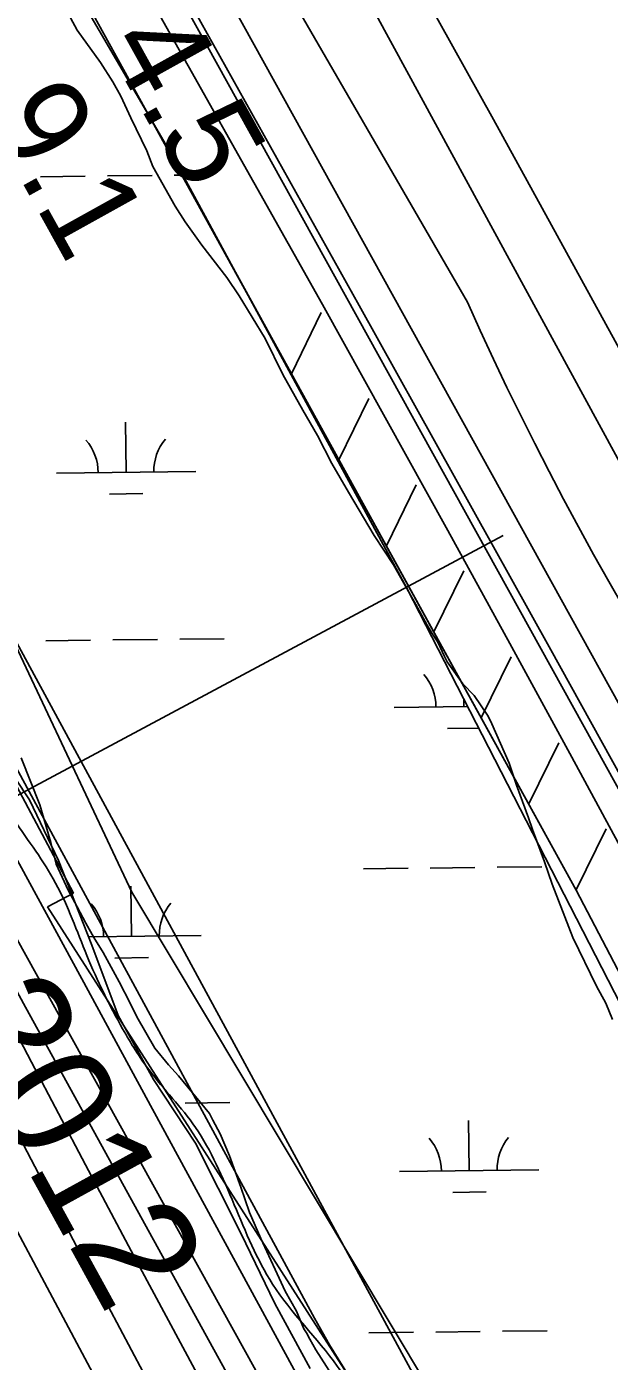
# Model space of a CAD drawing. Extents: x 3684037 to 3722149, y 433263 to 459021.
# Drawn here: x 3712383 to 3712801, y 439267 to 440224 of the extents above; entities that cross this region are included whole.
import ezdxf

# ---------------------------------------------------------------- set-up
doc = ezdxf.new("R2010")
doc.units = 0
for name, color, linetype in [('V-FLOD-BASE', 7, 'Continuous'), ('V-LEVE-TOET', 7, 'Continuous'), ('V-RIVR-EDGE', 7, 'Continuous'), ('V-RIVR-IDEN', 7, 'Continuous'), ('V-RIVR-RANG', 7, 'Continuous'), ('V-ROAD-CNTR', 7, 'Continuous'), ('V-RRAP-FSHR', 7, 'Continuous'), ('V-RRAP-RVMT', 7, 'Continuous'), ('V-SITE-VEGE', 7, 'Continuous'), ('V-SURV-LINE', 7, 'Continuous'), ('V-TOPO-DPTH', 7, 'Continuous'), ('V-TOPO-MINR', 7, 'Continuous'), ('V-TOPO-WATR', 7, 'Continuous'), ('V-UTIL-IDEN', 7, 'Continuous'), ('V-WETL-SWMP', 7, 'Continuous')]:
    doc.layers.add(name, color=color, linetype=linetype)

msp = doc.modelspace()

# ---------------------------------------------------------------- linework, layer by layer
at = {"layer": 'V-FLOD-BASE'}
for points in [[(3712621.19, 440024.51), (3712489.35, 440260.24), (3712460.31, 440309.47)], [(3713166.87, 438967.27), (3713140.61, 439026), (3713120.53, 439071.3), (3713100.22, 439116.51), (3713079.69, 439161.61), (3713058.93, 439206.61), (3713037.95, 439251.51), (3713016.74, 439296.3), (3712995.31, 439340.99), (3712973.66, 439385.56), (3712923.99, 439475.9), (3712874.6, 439566.38), (3712825.48, 439657.01), (3712757.58, 439779.62), (3712689.48, 439902.12), (3712621.19, 440024.51)]]:
    msp.add_lwpolyline(points, dxfattribs=at)
at = {"layer": 'V-LEVE-TOET'}
for points in [[(3711516.68, 442246.95), (3711627.09, 442006.55), (3711773.51, 441696.66), (3711965.19, 441335.23), (3712141.19, 441012.62), (3712263.15, 440800.06), (3712414.75, 440519.15), (3712489.08, 440395.79), (3712504.77, 440365.67), (3712551.23, 440281.69), (3712698.85, 440026.88)], [(3712594.9, 440025.08), (3712449.12, 440283.98), (3712438.67, 440303.09), (3712428.22, 440316.99), (3712416.03, 440329.72), (3712408.48, 440342.46), (3712402.09, 440356.95), (3712396.85, 440373.75), (3712391.04, 440388.23), (3712382.9, 440407.34), (3712366.65, 440432.25), (3712222.6, 440696.36), (3712039.64, 441028.82), (3711814.87, 441429.61), (3711723.69, 441588.89), (3711716.72, 441602.79), (3711694.64, 441649.13), (3711565.06, 441926.01), (3711441.87, 442202.32)], [(3712594.9, 440025.08), (3712639.93, 439944.15), (3712684.75, 439863.11), (3712729.36, 439781.95), (3712773.76, 439700.68), (3712817.94, 439619.29), (3712860.09, 439541.58), (3712902.44, 439463.98), (3712945.01, 439386.5), (3712956.33, 439363.85), (3712967.47, 439341.09), (3712978.41, 439318.25), (3712989.17, 439295.32), (3712999.74, 439272.29), (3713010.11, 439249.19), (3713020.3, 439225.99), (3713030.29, 439202.71), (3713040.09, 439179.35), (3713064.86, 439124.73), (3713089.81, 439070.2), (3713114.95, 439015.75), (3713137.67, 438966.93)], [(3712811.69, 439806.93), (3712800.46, 439826.41), (3712789.42, 439845.99), (3712778.57, 439865.69), (3712767.92, 439885.49), (3712757.46, 439905.4), (3712747.2, 439925.4), (3712737.13, 439945.51), (3712727.26, 439965.71), (3712717.59, 439986.01), (3712708.12, 440006.4), (3712698.85, 440026.88)]]:
    msp.add_lwpolyline(points, dxfattribs=at)
at = {"layer": 'V-RIVR-EDGE'}
msp.add_spline([(3710881.85, 442907.17), (3710900.3, 442872.76), (3710912.89, 442844.25), (3710926.84, 442815.27), (3710939.89, 442789.92), (3710950.22, 442762.31), (3710961.88, 442723.85), (3710972.69, 442706.64), (3710987.55, 442681.29), (3711004.19, 442645.52), (3711013.15, 442612.95), (3711017.62, 442590.33), (3711028.39, 442559.55), (3711043.23, 442525.61), (3711061.24, 442493.46), (3711083.32, 442464.01), (3711101.79, 442435.48), (3711123.37, 442385.69), (3711146.29, 442329.57), (3711160.2, 442285.22), (3711177.71, 442238.15), (3711205.6, 442178.4), (3711227.63, 442127.25), (3711258.71, 442079.24), (3711273.08, 442038.51), (3711277.08, 442009.57), (3711279.27, 441982.43), (3711285.11, 441965.69), (3711299.53, 441946.66), (3711314.4, 441925.82), (3711322.93, 441901.39), (3711344.09, 441864.26), (3711361.61, 441818.09), (3711381.38, 441766.05), (3711387.6, 441724.88), (3711408.3, 441685.04), (3711430.33, 441634.35), (3711446.97, 441597.23), (3711483.42, 441524.79), (3711505.9, 441474.1), (3711521.64, 441439.69), (3711545.49, 441393.97), (3711577.41, 441319.28), (3711605.29, 441255.01), (3711666.49, 441137.74), (3711693.94, 441084.32), (3711722.25, 441011.45), (3711736.18, 440977.51), (3711773.54, 440908.24), (3711800.07, 440850.29), (3711813.99, 440812.28), (3711827.94, 440785.11), (3711836.49, 440767.46), (3711872.07, 440711.3), (3711903.57, 440647.92), (3711936.4, 440576.4), (3711963.82, 440513.48), (3711991.74, 440467.29), (3712009.3, 440437.41), (3712020.05, 440394.43), (3712026.76, 440365.47), (3712043.42, 440336.04), (3712066.37, 440292.58), (3712088.89, 440257.25), (3712109.18, 440235.05), (3712138.9, 440183.88), (3712150.57, 440149.03), (3712155.9, 440111.04), (3712162.18, 440090.68), (3712177.89, 440044.52), (3712191.39, 440016), (3712212.53, 439972.54), (3712246.76, 439918.65), (3712265.21, 439881.98), (3712282.72, 439834), (3712320.51, 439756.14), (3712342.1, 439710.42), (3712373.62, 439655.63), (3712403.35, 439610.34), (3712425.83, 439558.28), (3712451.47, 439505.77), (3712470.39, 439476.33), (3712503.75, 439435.1), (3712518.6, 439408.84), (3712544.23, 439350.45), (3712559.09, 439322.83), (3712605.51, 439263.94), (3712623.98, 439233.6), (3712641.51, 439193.31), (3712662.18, 439142.17), (3712689.17, 439086.03), (3712722.5, 439033.5), (3712753.58, 438981.88), (3712765.15, 438962.6)], degree=3, dxfattribs=at)
at = {"layer": 'V-RIVR-RANG'}
msp.add_line((3712724.5, 439859.46), (3711895.41, 439416.5), dxfattribs=at)
at = {"layer": 'V-ROAD-CNTR'}
msp.add_lwpolyline([(3710393.02, 444727.69), (3710641.61, 444250), (3710817.86, 443893.88), (3711037.73, 443419.98), (3711197.76, 443070.03), (3711490.99, 442422.97), (3711750.12, 441857.32), (3711840.88, 441668.92), (3712186.17, 441036.48), (3712590.75, 440311.07), (3712879.98, 439780.16), (3713036.49, 439491.2), (3713175.22, 439193.41), (3713278.17, 438972.16)], dxfattribs=at)
at = {"layer": 'V-RRAP-FSHR'}
for p, q in [((3712572.55, 439975.43), (3712594.02, 440019.29)), ((3712572.55, 439975.43), (3712594.02, 440019.29)), ((3712606.63, 439913.76), (3712628.1, 439957.61)), ((3712606.63, 439913.76), (3712628.1, 439957.61)), ((3712640.7, 439852.08), (3712662.17, 439895.94)), ((3712640.7, 439852.08), (3712662.17, 439895.94)), ((3712674.78, 439790.41), (3712696.24, 439834.27)), ((3712674.78, 439790.41), (3712696.24, 439834.27)), ((3712708.85, 439728.74), (3712730.32, 439772.6)), ((3712708.85, 439728.74), (3712730.32, 439772.6)), ((3712742.92, 439667.06), (3712764.39, 439710.92)), ((3712742.92, 439667.06), (3712764.39, 439710.92)), ((3712777, 439605.39), (3712798.46, 439649.25)), ((3712777, 439605.39), (3712798.46, 439649.25))]:
    msp.add_line(p, q, dxfattribs=at)
for points in [[(3710219.36, 444700.16), (3710405.05, 444328.82), (3710632.08, 443905.61), (3710829.82, 443472.46), (3710874.19, 443372.05), (3710940.18, 443211.19), (3711150.7, 442775.78), (3711369.41, 442270.41), (3711583.94, 441827.2), (3711640.29, 441693.5), (3711911.6, 441196.46), (3712334.08, 440407.06), (3712777.04, 439605.31), (3712909.03, 439353.17), (3713100.31, 438966.64)], [(3710449.88, 443948.54), (3711032.4, 442732.84), (3711461.51, 441700.35), (3711800.31, 440955.81), (3712037.99, 440494.59), (3712458, 439603.75), (3712696.92, 439205.07), (3712836.7, 438963.43)], [(3712532.33, 440048.23), (3712777.04, 439605.31), (3712909.03, 439353.17), (3713100.31, 438966.64)]]:
    msp.add_lwpolyline(points, dxfattribs=at)
at = {"layer": 'V-RRAP-RVMT'}
for p, q in [((3712349.23, 439728.84), (3712416.17, 439603.02)), ((3712416.17, 439603.02), (3712397.44, 439593.28)), ((3712397.44, 439593.28), (3712704.29, 439115.64))]:
    msp.add_line(p, q, dxfattribs=at)
at = {"layer": 'V-SITE-VEGE'}
for p, q in [((3712414.12, 440230.75), (3712418.88, 440221.89)), ((3712418.88, 440221.89), (3712435.46, 440198.62)), ((3712435.46, 440198.62), (3712444.47, 440184.65)), ((3712444.47, 440184.65), (3712450.17, 440174.4)), ((3712450.17, 440174.4), (3712457.32, 440159.01)), ((3712457.32, 440159.01), (3712468.75, 440135.23)), ((3712468.75, 440135.23), (3712473.06, 440124.03)), ((3712473.06, 440124.03), (3712489.21, 440095.6)), ((3712489.21, 440095.6), (3712496.32, 440084.43)), ((3712496.32, 440084.43), (3712508.17, 440067.67)), ((3712508.17, 440067.67), (3712526.15, 440044.41)), ((3712526.15, 440044.41), (3712535.15, 440031.38)), ((3712535.15, 440031.38), (3712553.66, 440000.63)), ((3712553.66, 440000.63), (3712566.52, 439974.99)), ((3712566.52, 439974.99), (3712580.77, 439949.36)), ((3712580.77, 439949.36), (3712591.22, 439931.18)), ((3712591.22, 439931.18), (3712601.68, 439911.14)), ((3712601.68, 439911.14), (3712613.56, 439890.64)), ((3712613.56, 439890.64), (3712632.07, 439859.42)), ((3712632.07, 439859.42), (3712645.82, 439838.47)), ((3712645.82, 439838.47), (3712661.97, 439810.05)), ((3712661.97, 439810.05), (3712670.06, 439795.13)), ((3712670.06, 439795.13), (3712674.33, 439788.15)), ((3712674.33, 439788.15), (3712677.65, 439783.02)), ((3712677.65, 439783.02), (3712682.41, 439772.76)), ((3712682.41, 439772.76), (3712684.32, 439769.03)), ((3712684.32, 439769.03), (3712695.68, 439753.21)), ((3712695.68, 439753.21), (3712703.71, 439744.85)), ((3712703.71, 439744.85), (3712713.67, 439729.95)), ((3712713.67, 439729.95), (3712716.52, 439724.36)), ((3712716.52, 439724.36), (3712728.92, 439696.37)), ((3712392.1, 439666.44), (3712378.71, 439700.03)), ((3712728.92, 439696.37), (3712734.2, 439680.49)), ((3712734.2, 439680.49), (3712742.82, 439657.16)), ((3712394.99, 439656.63), (3712392.1, 439666.44)), ((3712399.81, 439639.35), (3712394.99, 439656.63)), ((3712742.82, 439657.16), (3712745.7, 439648.75)), ((3712745.7, 439648.75), (3712754.32, 439625.42)), ((3712403.68, 439623.93), (3712399.81, 439639.35)), ((3712412.27, 439605.27), (3712403.68, 439623.93)), ((3712754.32, 439625.42), (3712759.6, 439609.54)), ((3712418.92, 439593.16), (3712412.27, 439605.27)), ((3712759.6, 439609.54), (3712768.69, 439586.21)), ((3712425.1, 439581.5), (3712418.92, 439593.16)), ((3712768.69, 439586.21), (3712774.43, 439571.28)), ((3712430.8, 439571.25), (3712425.1, 439581.5)), ((3712437.44, 439560.54), (3712430.8, 439571.25)), ((3712774.43, 439571.28), (3712791.57, 439536.31)), ((3712448.85, 439539.57), (3712437.44, 439560.54)), ((3712456.94, 439524.18), (3712448.85, 439539.57)), ((3712791.57, 439536.31), (3712798.23, 439524.19)), ((3712461.7, 439514.39), (3712456.94, 439524.18)), ((3712798.23, 439524.19), (3712803.01, 439512.53)), ((3712474.52, 439492.03), (3712461.7, 439514.39)), ((3712484.46, 439479.94), (3712474.52, 439492.03)), ((3712491.54, 439472.04), (3712484.46, 439479.94)), ((3712513.77, 439445.07), (3712491.54, 439472.04)), ((3712516.15, 439440.4), (3712513.77, 439445.07)), ((3712521.38, 439430.62), (3712516.15, 439440.4)), ((3712528.07, 439414.75), (3712521.38, 439430.62)), ((3712536.21, 439392.35), (3712528.07, 439414.75)), ((3712542.45, 439374.14), (3712536.21, 439392.35)), ((3712550.56, 439355.48), (3712542.45, 439374.14)), ((3712568.19, 439317.71), (3712550.56, 439355.48)), ((3712576.27, 439303.26), (3712568.19, 439317.71)), ((3712581.52, 439290.66), (3712576.27, 439303.26)), ((3712583.42, 439287.87), (3712581.52, 439290.66)), ((3712585.8, 439283.21), (3712583.42, 439287.87)), ((3712590.07, 439275.75), (3712585.8, 439283.21)), ((3712610.94, 439243.15), (3712590.07, 439275.75))]:
    msp.add_line(p, q, dxfattribs=at)
at = {"layer": 'V-SURV-LINE'}
for points in [[(3711755.82, 441636.9), (3712986.54, 439416.05)], [(3712960.3, 439401.52), (3711729.57, 441622.37)]]:
    msp.add_lwpolyline(points, dxfattribs=at)
at = {"layer": 'V-TOPO-DPTH'}
for points in [[(3712711.91, 438961.98), (3712683.26, 439014.44), (3712669.9, 439038.84), (3712656.51, 439063.23), (3712643.07, 439087.58), (3712629.6, 439111.92), (3712159.9, 439958.74), (3711790.59, 440757.32)], [(3711790.59, 440757.32), (3712159.9, 439958.74), (3712629.6, 439111.92), (3712643.07, 439087.58), (3712656.51, 439063.23), (3712669.9, 439038.84), (3712683.26, 439014.44), (3712711.91, 438961.98)], [(3712775.94, 438962.72), (3712772.45, 438970), (3712768.37, 438979.09), (3712764.64, 438988.33), (3712761.15, 438997.67), (3712756.93, 439009.65), (3712755.87, 439013.11), (3712755, 439016.6), (3712754.42, 439020.15), (3712754.04, 439023.75), (3712753.61, 439027.32), (3712752.94, 439030.84), (3712751.9, 439034.26), (3712599.91, 439279.32), (3712589.26, 439298.44), (3712232.32, 439956.11), (3712223.41, 439972.67), (3712214.6, 439989.28), (3712205.92, 440005.96), (3712197.32, 440022.68), (3711902.32, 440602.62)], [(3712630.61, 438961.03), (3712603, 439008.9), (3712598.54, 439016.71), (3712594.12, 439024.53), (3712589.75, 439032.38), (3712585.42, 439040.26), (3712508.55, 439181.19), (3712466.17, 439259.74), (3712424.26, 439338.53), (3712383.05, 439417.7), (3712342.32, 439497.11), (3712140.47, 439895.05), (3712130.14, 439915.69), (3712119.96, 439936.41), (3712109.99, 439957.23), (3712100.18, 439978.12), (3711852.57, 440512.66)], [(3711852.57, 440512.66), (3712100.18, 439978.12), (3712109.99, 439957.23), (3712119.96, 439936.41), (3712130.14, 439915.69), (3712140.47, 439895.05), (3712342.32, 439497.11), (3712383.05, 439417.7), (3712424.26, 439338.53), (3712466.17, 439259.74), (3712508.55, 439181.19), (3712585.42, 439040.26), (3712589.75, 439032.38), (3712594.12, 439024.53), (3712598.54, 439016.71), (3712603, 439008.9), (3712630.61, 438961.03)], [(3711979.56, 440292.74), (3712019.96, 440206.64), (3712060.55, 440120.63), (3712133.23, 439967.27), (3712137.67, 439958.03), (3712142.19, 439948.84), (3712146.81, 439939.69), (3712151.5, 439930.58), (3712386.11, 439482), (3712424.88, 439408.36), (3712463.91, 439334.85), (3712503.34, 439261.56), (3712543.03, 439188.41), (3712582.5, 439116.14), (3712602.71, 439079.27), (3712623, 439042.43), (3712643.4, 439005.66), (3712663.88, 438968.93), (3712666.87, 438963.6), (3712668.06, 438961.47)], [(3711979.56, 440292.74), (3712019.96, 440206.64), (3712060.55, 440120.63), (3712133.23, 439967.27), (3712137.67, 439958.03), (3712142.19, 439948.84), (3712146.81, 439939.69), (3712151.5, 439930.58), (3712386.11, 439482), (3712424.88, 439408.36), (3712463.91, 439334.85), (3712503.34, 439261.56), (3712543.03, 439188.41), (3712582.5, 439116.14), (3712602.71, 439079.27), (3712623, 439042.43), (3712643.4, 439005.66), (3712663.88, 438968.93), (3712666.87, 438963.6), (3712668.06, 438961.47)], [(3712590.85, 438960.57), (3712590.74, 438960.77), (3712577.83, 438983.59), (3712565.06, 439006.49), (3712552.48, 439029.5), (3712540.03, 439052.58), (3712182.61, 439722.15), (3712165.69, 439754.27), (3712148.99, 439786.51), (3712132.64, 439818.92), (3712116.52, 439851.46), (3712100.72, 439884.15), (3712085.12, 439916.94), (3712069.84, 439949.87), (3712054.75, 439982.89), (3712000.27, 440103.65), (3711958.26, 440197.2), (3711916.46, 440290.85)], [(3712590.85, 438960.57), (3712590.74, 438960.77), (3712577.83, 438983.59), (3712565.06, 439006.49), (3712552.48, 439029.5), (3712540.03, 439052.58), (3712182.61, 439722.15), (3712165.69, 439754.27), (3712148.99, 439786.51), (3712132.64, 439818.92), (3712116.52, 439851.46), (3712100.72, 439884.15), (3712085.12, 439916.94), (3712069.84, 439949.87), (3712054.75, 439982.89), (3712000.27, 440103.65), (3711958.26, 440197.2), (3711916.46, 440290.85)]]:
    msp.add_lwpolyline(points, dxfattribs=at)
at = {"layer": 'V-TOPO-MINR'}
for points in [[(3712690.03, 438961.73), (3712670.77, 438996.58), (3712655.24, 439024.69), (3712639.72, 439052.81), (3712624.21, 439080.94), (3712608.71, 439109.07), (3712381.75, 439521.26), (3712342.55, 439592.95), (3712303.64, 439664.79), (3712265.15, 439736.86), (3712226.94, 439809.08), (3712155.72, 439944.67), (3712153.36, 439949.22), (3712151.04, 439953.79), (3712148.78, 439958.39), (3712146.55, 439963), (3712109.43, 440041.15), (3712088.74, 440084.88), (3712068.15, 440128.66), (3712047.7, 440172.51), (3712027.35, 440216.4), (3711775.13, 440762.6)], [(3712711.91, 438961.98), (3712683.26, 439014.44), (3712669.9, 439038.84), (3712656.51, 439063.23), (3712643.07, 439087.58), (3712629.6, 439111.92), (3712159.9, 439958.74), (3711790.59, 440757.32)], [(3712630.61, 438961.03), (3712603, 439008.9), (3712598.54, 439016.71), (3712594.12, 439024.53), (3712589.75, 439032.38), (3712585.42, 439040.26), (3712508.55, 439181.19), (3712466.17, 439259.74), (3712424.26, 439338.53), (3712383.05, 439417.7), (3712342.32, 439497.11), (3712140.47, 439895.05), (3712130.14, 439915.69), (3712119.96, 439936.41), (3712109.99, 439957.23), (3712100.18, 439978.12), (3711852.57, 440512.66)], [(3712668.06, 438961.47), (3712666.87, 438963.6), (3712663.88, 438968.93), (3712643.4, 439005.66), (3712623, 439042.43), (3712602.71, 439079.27), (3712582.5, 439116.14), (3712543.03, 439188.41), (3712503.34, 439261.56), (3712463.91, 439334.85), (3712424.88, 439408.36), (3712386.11, 439482), (3712151.5, 439930.58), (3712146.81, 439939.69), (3712142.19, 439948.84), (3712137.67, 439958.03), (3712133.23, 439967.27), (3712060.55, 440120.63), (3712019.96, 440206.64), (3711979.56, 440292.74)], [(3712590.85, 438960.57), (3712590.74, 438960.77), (3712577.83, 438983.59), (3712565.06, 439006.49), (3712552.48, 439029.5), (3712540.03, 439052.58), (3712182.61, 439722.15), (3712165.69, 439754.27), (3712148.99, 439786.51), (3712132.64, 439818.92), (3712116.52, 439851.46), (3712100.72, 439884.15), (3712085.12, 439916.94), (3712069.84, 439949.87), (3712054.75, 439982.89), (3712000.27, 440103.65), (3711958.26, 440197.2), (3711916.46, 440290.85)], [(3712736.43, 438962.27), (3712712.94, 439006.14), (3712694.4, 439040.69), (3712675.81, 439075.2), (3712657.14, 439109.68), (3712638.42, 439144.12), (3712574.33, 439261.75), (3712523.55, 439355.01), (3712472.81, 439448.28), (3712422.11, 439541.59), (3712371.45, 439634.91), (3712220.08, 439913.93), (3712203.92, 439944.11), (3712187.99, 439974.41), (3712172.4, 440004.88), (3712157.04, 440035.47), (3712087.75, 440175.37), (3712038.19, 440276.14)], [(3712819.96, 438963.24), (3712375.6, 439782.6), (3712346.28, 439817.89), (3712320, 439855.5), (3712295.75, 439894.66), (3712242.22, 439989.76), (3712239.06, 439995.47), (3712235.95, 440001.21), (3712232.94, 440007), (3712229.97, 440012.81), (3712146.88, 440178.99), (3712102.85, 440268.13)]]:
    msp.add_lwpolyline(points, dxfattribs=at)
at = {"layer": 'V-TOPO-WATR'}
msp.add_lwpolyline([(3712775.94, 438962.72), (3712772.45, 438970), (3712768.37, 438979.09), (3712764.64, 438988.33), (3712761.15, 438997.67), (3712756.93, 439009.65), (3712755.87, 439013.11), (3712755, 439016.6), (3712754.42, 439020.15), (3712754.04, 439023.75), (3712753.61, 439027.32), (3712752.94, 439030.84), (3712751.9, 439034.26), (3712599.91, 439279.32), (3712589.26, 439298.44), (3712232.32, 439956.11), (3712223.41, 439972.67), (3712214.6, 439989.28), (3712205.92, 440005.96), (3712197.32, 440022.68), (3711902.32, 440602.62)], dxfattribs=at)
at = {"layer": 'V-UTIL-IDEN'}
for points in [[(3710219.36, 444700.16), (3710405.05, 444328.82), (3710632.08, 443905.61), (3710829.82, 443472.46), (3710874.19, 443372.05), (3710940.18, 443211.19), (3711150.7, 442775.78), (3711369.41, 442270.41), (3711583.94, 441827.2), (3711640.29, 441693.5), (3711911.6, 441196.46), (3712334.08, 440407.06), (3712777.04, 439605.31), (3712909.03, 439353.17), (3713100.31, 438966.64)], [(3712532.33, 440048.23), (3712777.04, 439605.31), (3712909.03, 439353.17), (3713100.31, 438966.64)]]:
    msp.add_lwpolyline(points, dxfattribs=at)
at = {"layer": 'V-WETL-SWMP'}
for p, q in [((3712205.56, 440614.23), (3712487.72, 440130.65)), ((3712529.3, 440495.9), (3712717.61, 440157.75)), ((3712717.61, 440157.75), (3712885.78, 439851.46)), ((3712487.72, 440130.65), (3712655.52, 439821.79)), ((3712392.56, 440116.7), (3712424.55, 440117.07)), ((3712440.55, 440117.25), (3712472.55, 440117.63)), ((3712488.55, 440117.81), (3712494.66, 440117.88)), ((3712453.87, 439904.79), (3712453.45, 439940.79)), ((3712403.87, 439904.21), (3712503.87, 439905.37)), ((3712442.05, 439889.22), (3712466.05, 439889.5)), ((3712655.52, 439821.79), (3712851.98, 439439.12)), ((3712492.42, 439785.16), (3712524.42, 439785.53)), ((3712396.43, 439784.04), (3712428.42, 439784.42)), ((3712444.42, 439784.6), (3712476.42, 439784.97)), ((3712696.31, 439736.79), (3712696.25, 439742.46)), ((3712646.32, 439736.21), (3712699.14, 439736.82)), ((3712684.49, 439721.22), (3712707.02, 439721.48)), ((3712384.72, 439669.9), (3712363.42, 439701.69)), ((3712405.35, 439626.42), (3712384.72, 439669.9)), ((3712429.23, 439565.82), (3712405.35, 439626.42)), ((3712624.25, 439620.51), (3712656.25, 439620.88)), ((3712672.25, 439621.07), (3712704.25, 439621.44)), ((3712720.25, 439621.63), (3712752.24, 439622)), ((3712457.74, 439572.14), (3712457.32, 439608.14)), ((3712426.88, 439571.78), (3712507.74, 439572.72)), ((3712448.36, 439515.31), (3712429.23, 439565.82)), ((3712445.92, 439556.57), (3712469.92, 439556.85)), ((3712473.68, 439469.53), (3712448.36, 439515.31)), ((3712503.67, 439423.78), (3712473.68, 439469.53)), ((3712496.29, 439452.51), (3712528.29, 439452.88)), ((3712700.18, 439404.13), (3712699.77, 439440.13)), ((3712536.16, 439359.35), (3712503.67, 439423.78)), ((3712650.19, 439403.55), (3712750.18, 439404.72)), ((3712688.36, 439388.57), (3712712.36, 439388.84)), ((3712560.74, 439308.89), (3712536.16, 439359.35)), ((3712586.07, 439262.33), (3712560.74, 439308.89)), ((3712628.12, 439287.86), (3712660.12, 439288.23)), ((3712676.12, 439288.42), (3712708.12, 439288.79)), ((3712724.12, 439288.97), (3712756.12, 439289.35))]:
    msp.add_line(p, q, dxfattribs=at)
for centre, start, end in [((3712509.1, 439905.91), 139.89487, 181.43852), ((3712398.63, 439904.62), 359.89487, 41.43852), ((3712641.07, 439736.62), 359.89487, 41.43852), ((3712402.5, 439571.97), 359.89487, 41.43852), ((3712512.97, 439573.26), 139.89487, 181.43852), ((3712644.94, 439403.97), 359.89487, 41.43852), ((3712755.42, 439405.25), 139.89487, 181.43852)]:
    msp.add_arc(centre, 35.25, start, end, dxfattribs=at)

# ---------------------------------------------------------------- texts
at = {"layer": 'V-RIVR-IDEN'}
msp.add_text('2012', height=83, rotation=298.80526, dxfattribs=at).set_placement((3712322.27, 439515.01))
at = {"layer": 'V-RIVR-RANG'}
for s, p in [('4.5', (3712438.36, 440212.23)), ('9.1', (3712352.2, 440161.4))]:
    msp.add_text(s, height=67, rotation=299.03833, dxfattribs=at).set_placement(p)

doc.saveas('drawing.dxf')
